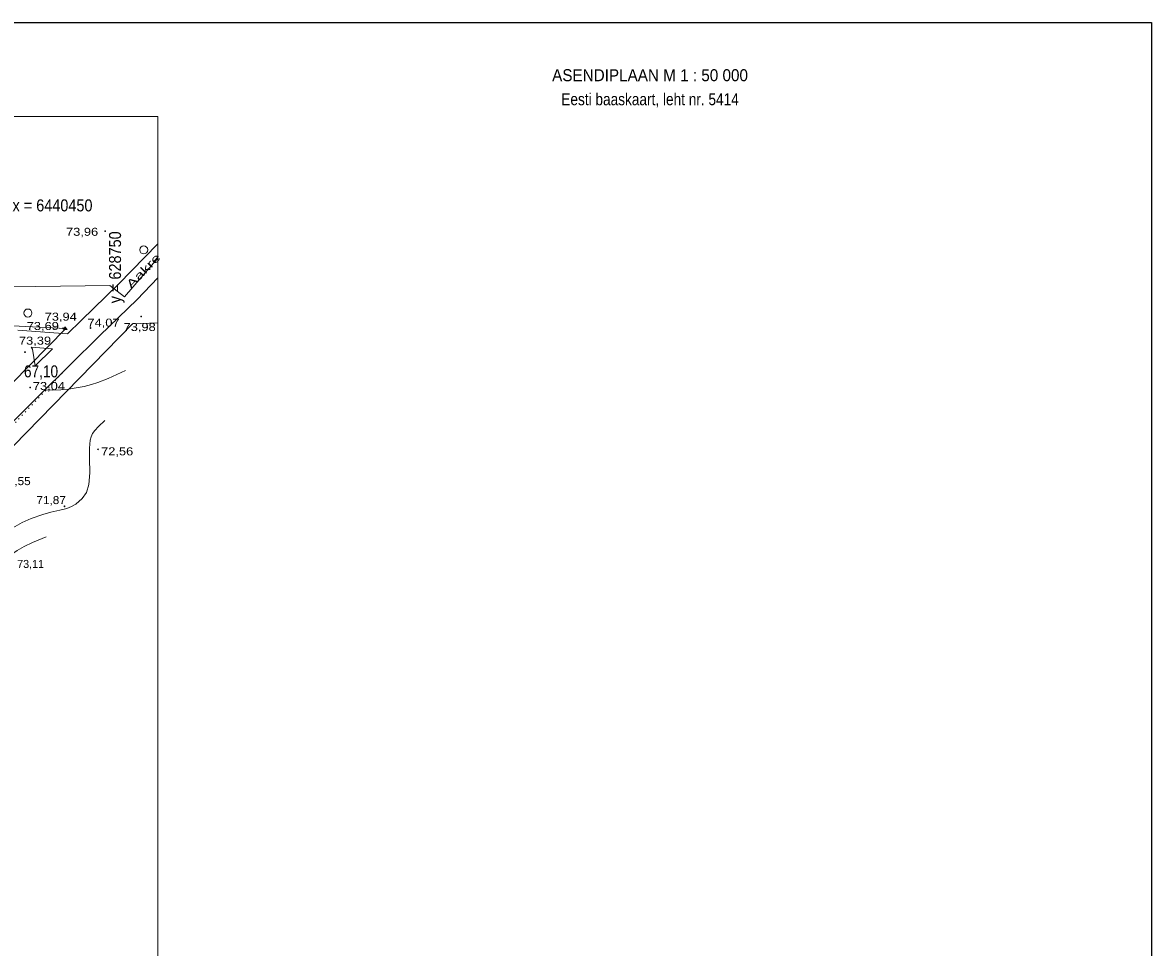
# Model space of a CAD drawing. Extents: x 628176 to 629009, y 6439913 to 6440496.
# Drawn here: x 628726.4 to 629008.5, y 6440264.8 to 6440495.9 of the extents above; entities that cross this region are included whole.
import ezdxf
from ezdxf.enums import TextEntityAlignment as Align

# ---------------------------------------------------------------- set-up
doc = ezdxf.new("R2010")
doc.units = 0
doc.header["$LTSCALE"] = 0.8
doc.linetypes.add('DOTTED', pattern=[1.5, 0.3, -1.2])
for name, color, linetype, lineweight in [('1', 7, 'Continuous', 13), ('12', 7, 'Continuous', 13), ('3', 7, 'Continuous', 13), ('50', 7, 'Continuous', 13), ('6', 7, 'Continuous', 13)]:
    doc.layers.add(name, color=color, linetype=linetype, lineweight=lineweight)
doc.layers.add('4', color=7, linetype='Continuous')

msp = doc.modelspace()

# ---------------------------------------------------------------- hatches: boundary and pattern name
at = {"layer": '1'}
for points in [[(628747.1355, 6440443.7659, 1), (628746.9355, 6440443.7659, 1)], [(628756.167, 6440422.475, 1), (628755.967, 6440422.475, 1)], [(628736.6391, 6440419.4985, 1), (628736.4391, 6440419.4985, 1)], [(628737.1889, 6440419.4909, 1), (628736.9889, 6440419.4909, 1)], [(628743.4563, 6440419.5974, 1), (628743.2563, 6440419.5974, 1)], [(628727.1179, 6440413.5705, 1), (628726.9179, 6440413.5705, 1)], [(628728.4242, 6440404.7456, 1), (628728.2242, 6440404.7456, 1)], [(628745.3519, 6440389.2699, 1), (628745.1519, 6440389.2699, 1)], [(628736.9796, 6440375.0235, 1), (628736.7796, 6440375.0235, 1)]]:
    msp.add_hatch(color=256, dxfattribs=at).paths.add_polyline_path(points)

# ---------------------------------------------------------------- linework, layer by layer
for p, q in [((628760.23, 6440440.64), (628750.39, 6440430.57)), ((628760.23, 6440432.09), (628755.02, 6440426.75)), ((628750.39, 6440430.57), (628741.03, 6440421.49)), ((628755.02, 6440426.75), (628745.69, 6440417.71)), ((628737.09, 6440419.49), (628736.84, 6440419.49)), ((628737.09, 6440419.49), (628737.09, 6440419.74)), ((628737.09, 6440419.49), (628737.34, 6440419.49)), ((628737.09, 6440419.49), (628737.09, 6440419.24)), ((628737.64, 6440418.15), (628741.03, 6440421.49)), ((628737.64, 6440418.15), (628725.2, 6440419.05)), ((628730.57, 6440402.75), (628745.69, 6440417.71)), ((628728.58, 6440414.8), (628728.89, 6440414.26)), ((628733.87, 6440414.42), (628728.58, 6440414.8)), ((628728.89, 6440414.26), (628729.52, 6440410.13)), ((628729.52, 6440410.13), (628733.87, 6440414.42)), ((628717.21, 6440389.44), (628730.57, 6440402.75))]:
    msp.add_line(p, q, dxfattribs=at)
msp.add_lwpolyline([(628737, 6440419.89), (628736.62, 6440419.25), (628737.51, 6440419.25)], close=True, dxfattribs=at)
at = {"layer": '1', "linetype": 'DOTTED', "lineweight": 25}
msp.add_lwpolyline([(628691.92, 6440361.9), (628718, 6440389), (628737.89, 6440410)], dxfattribs=at)
at = {"layer": '1'}
for centre, radius in [((628747.0355, 6440443.7659), 0.1), ((628756.6887, 6440439.1054), 1), ((628727.7338, 6440423.3353), 1), ((628756.067, 6440422.475), 0.1), ((628736.5391, 6440419.4985), 0.1), ((628737.0889, 6440419.4909), 0.1), ((628743.3563, 6440419.5974), 0.1), ((628727.0179, 6440413.5705), 0.1), ((628728.3242, 6440404.7456), 0.1), ((628745.2519, 6440389.2699), 0.1), ((628736.8796, 6440375.0235), 0.1)]:
    msp.add_circle(centre, radius, dxfattribs=at)
at = {"layer": '3'}
for p, q in [((628737.85, 6440404.34), (628736, 6440404.16)), ((628740.34, 6440404.72), (628737.85, 6440404.34)), ((628743.31, 6440391.56), (628743.11, 6440389.58)), ((628743.31, 6440391.56), (628743.54, 6440392.42)), ((628743.54, 6440392.42), (628743.87, 6440393.19)), ((628743.87, 6440393.19), (628744.44, 6440394)), ((628743.11, 6440387), (628743.11, 6440389.58))]:
    msp.add_line(p, q, dxfattribs=at)
for points in [[(628740.34, 6440404.72), (628741.77, 6440405), (628743.62, 6440405.5), (628745.21, 6440406), (628747.83, 6440407), (628752.16, 6440409)], [(628731.95, 6440404.12), (628734, 6440404.06), (628736, 6440404.16)], [(628744.44, 6440394), (628745.35, 6440395), (628747, 6440396.49)], [(628735.69, 6440374.07), (628737.44, 6440374.52), (628738.67, 6440375), (628739.73, 6440375.58), (628741.31, 6440377), (628742.37, 6440378.52), (628743, 6440380.5), (628743.21, 6440383.4), (628743.11, 6440387)], [(628728.54, 6440372), (628726.27, 6440371), (628724, 6440369.68), (628720.63, 6440367.44)], [(628728.54, 6440372), (628731.43, 6440373), (628733.46, 6440373.59), (628735.69, 6440374.07)], [(628726.77, 6440365), (628728.85, 6440366), (628732.29, 6440367.44)], [(628726.77, 6440365), (628725.03, 6440364), (628723, 6440362.54), (628722, 6440361.47), (628721.43, 6440360), (628721.43, 6440359), (628722, 6440357), (628723, 6440355.42)]]:
    msp.add_lwpolyline(points, dxfattribs=at)
at = {"layer": '50', "lineweight": 25}
msp.add_lwpolyline([(628178.27, 6440495.9), (629008.51, 6440495.9), (629008.51, 6439918.47), (628178.27, 6439918.47)], close=True, dxfattribs=at)
at = {"layer": '50'}
msp.add_lwpolyline([(628214.18, 6440472.45), (628760.23, 6440472.45), (628760.23, 6440028.67), (628214.18, 6440028.67)], close=True, dxfattribs=at)
at = {"layer": '6'}
msp.add_line((628753.89, 6440420.62), (628760.23, 6440420.89), dxfattribs=at)
for points in [[(628617.76, 6440472.45), (628575.19, 6440427.91), (628575.26, 6440427.9), (628575.26, 6440427.9), (628748.21, 6440430.21), (628751.85, 6440427.4), (628760.23, 6440437.07)], [(628713.84, 6440420.66), (628737.18, 6440419.44), (628678.6, 6440359.86), (628654.6, 6440328.98), (628627.14, 6440290.88), (628627.14, 6440290.88), (628627.14, 6440290.88), (628562.66, 6440201.7), (628536.24, 6440148.38), (628489.22, 6440071.42), (628480.02, 6440052.78), (628457.03, 6440037.16), (628421.17, 6440028.67)], [(628753.89, 6440420.62), (628687.68, 6440352.8), (628636.46, 6440284.16), (628572.54, 6440195.74), (628546.32, 6440142.82), (628546.32, 6440142.82), (628546.32, 6440142.82), (628498.7, 6440064.9), (628484.24, 6440046.28), (628473.72, 6440036.18), (628464.05, 6440028.67)]]:
    msp.add_lwpolyline(points, dxfattribs=at)

# ---------------------------------------------------------------- texts
at = {"layer": '1'}
for s, width, p in [('73,96', 1.2, (628737.27, 6440442.63)), ('73,94', 1.2, (628731.93, 6440421.42)), ('73,69', 1.2, (628727.44, 6440419.09)), ('74,07', 1.2, (628742.62, 6440419.93)), ('73,98', 1.2, (628751.65, 6440418.84)), ('73,39', 1.2, (628725.5, 6440415.43)), ('73,04', 1.2, (628728.97, 6440404.09)), ('72,56', 1.2, (628746.03, 6440387.77)), ('71,55', 1.1, (628721.07, 6440380.33)), ('71,87', 1.1, (628729.86, 6440375.59))]:
    msp.add_text(s, height=2, dxfattribs=dict(at, width=width)).set_placement(p)
at = {"layer": '1', "width": 1.55}
msp.add_text('Aakre', height=2, rotation=45.872, dxfattribs=at).set_placement((628753.54, 6440429.29))
at = {"layer": '1'}
msp.add_text('73,11', height=2, dxfattribs=at).set_placement((628725.07, 6440359.64))
at = {"layer": '12', "width": 0.85}
msp.add_text('67,10', height=3, dxfattribs=at).set_placement((628731.015, 6440407.26), align=Align.CENTER)
at = {"layer": '4', "width": 0.9}
msp.add_text('x = 6440450', height=3, dxfattribs=at).set_placement((628723.9, 6440448.73))
msp.add_text('y = 628750', height=3, rotation=90, dxfattribs=at).set_placement((628751.01, 6440425.77))
at = {"layer": '50'}
for s, width, p in [('ASENDIPLAAN M 1 : 50 000', 0.95, (628883.215, 6440481.25)), ('Eesti baaskaart, leht nr. 5414', 0.85, (628883.215, 6440475.25))]:
    msp.add_text(s, height=3, dxfattribs=dict(at, width=width)).set_placement(p, align=Align.CENTER)

doc.saveas('drawing.dxf')
